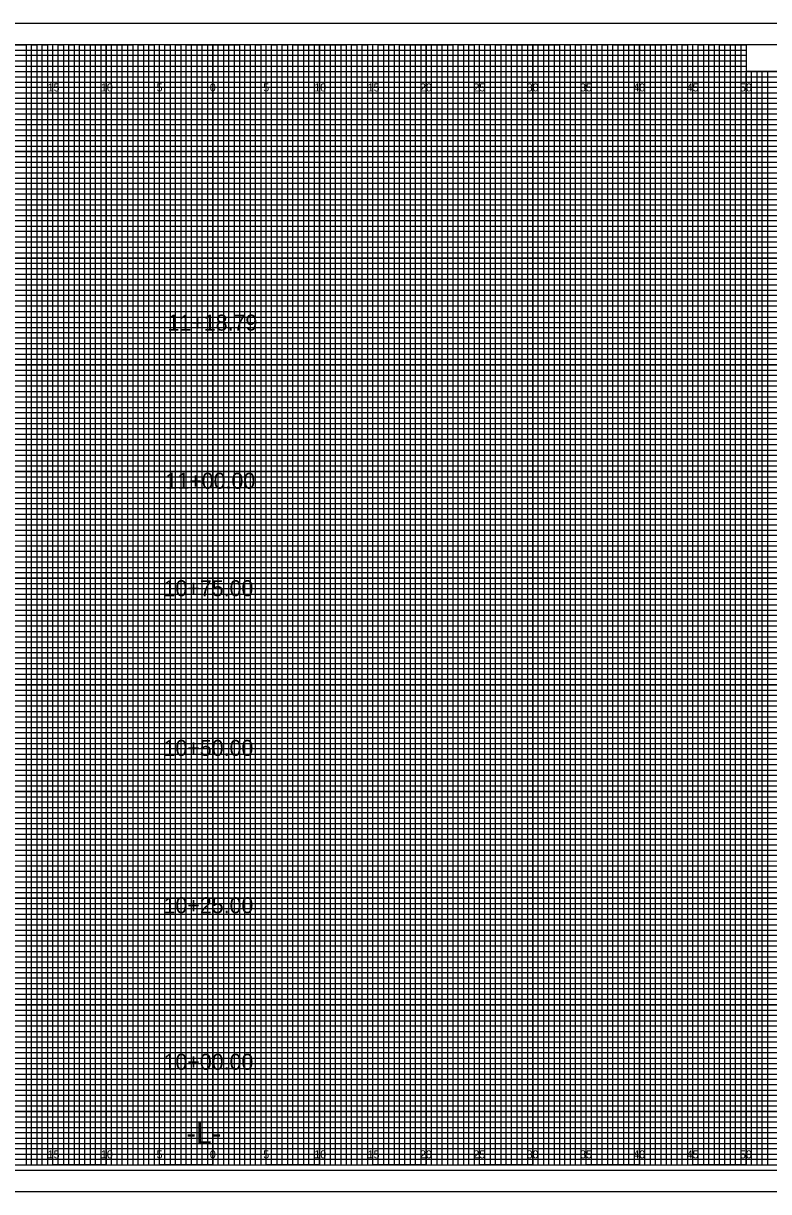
# Model space of a CAD drawing. Extents: x -7 to 205, y -2 to 107.
# Drawn here: x 62.2 to 132.1, y -2.5 to 107 of the extents above; entities that cross this region are included whole.
import ezdxf

# ---------------------------------------------------------------- set-up
doc = ezdxf.new("R2010")
doc.units = 0
for name, color, linetype in [('Prop XS Alignment Label', 7, 'Continuous'), ('Prop XS Offset Labels', 7, 'Continuous'), ('Prop XS Station Labels', 7, 'Continuous'), ('Sheet Cross Section CELL', 7, 'Continuous'), ('Sheet Cross Section Grid Major CELL', 7, 'Continuous'), ('Sheet Cross Section Grid Middle CELL', 7, 'Continuous'), ('Sheet Cross Section Grid Minor 1 CELL', 7, 'Continuous'), ('Sheet Cross Section Grid Minor 2 CELL', 7, 'Continuous'), ('Sheet Cutting Line CELL', 7, 'Continuous'), ('Sheet DOT Grid CELL', 7, 'Continuous'), ('Sheet Plot Border Inside CELL', 7, 'Continuous'), ('Sheet Plot Border Outside CELL', 7, 'Continuous')]:
    doc.layers.add(name, color=color, linetype=linetype)

msp = doc.modelspace()

# ---------------------------------------------------------------- linework, layer by layer
at = {"layer": 'Sheet Cross Section CELL'}
for points in [[(160, 105), (0, 105), (0, 0), (160, 0)], [(140, 105), (130, 105), (130, 102.52), (140, 102.52)]]:
    msp.add_lwpolyline(points, close=True, dxfattribs=at)
at = {"layer": 'Sheet Cross Section Grid Major CELL'}
for p, q in [((65, 105), (60, 105)), ((65, 0), (65, 105)), ((75, 105), (70, 105)), ((70, 105), (70, 0)), ((75, 0), (75, 105)), ((85, 105), (80, 105)), ((80, 105), (80, 0)), ((85, 0), (85, 105)), ((95, 105), (90, 105)), ((90, 105), (90, 0)), ((95, 0), (95, 105)), ((105, 105), (100, 105)), ((100, 105), (100, 0)), ((105, 0), (105, 105)), ((115, 105), (110, 105)), ((110, 105), (110, 0)), ((115, 0), (115, 105)), ((125, 105), (120, 105)), ((120, 105), (120, 0)), ((125, 0), (125, 105)), ((130, 105), (130, 0)), ((70, 0), (65, 0)), ((80, 0), (75, 0)), ((90, 0), (85, 0)), ((100, 0), (95, 0)), ((110, 0), (105, 0)), ((120, 0), (115, 0)), ((130, 0), (125, 0))]:
    msp.add_line(p, q, dxfattribs=at)
for points in [[(0, 100), (160, 100), (160, 95), (0, 95)], [(0, 90), (160, 90), (160, 85), (0, 85)], [(0, 80), (160, 80), (160, 75), (0, 75)], [(0, 70), (160, 70), (160, 65), (0, 65)], [(0, 60), (160, 60), (160, 55), (0, 55)], [(0, 50), (160, 50), (160, 45), (0, 45)], [(0, 40), (160, 40), (160, 35), (0, 35)], [(0, 30), (160, 30), (160, 25), (0, 25)], [(0, 20), (160, 20), (160, 15), (0, 15)], [(0, 10), (160, 10), (160, 5), (0, 5)]]:
    msp.add_lwpolyline(points, dxfattribs=at)
at = {"layer": 'Sheet Cross Section Grid Middle CELL'}
for points in [[(57.5, 105), (62.5, 105), (62.5, 0), (67.5, 0), (67.5, 105), (72.5, 105), (72.5, 0), (77.5, 0), (77.5, 105), (82.5, 105), (82.5, 0), (87.5, 0), (87.5, 105), (92.5, 105), (92.5, 0), (97.5, 0), (97.5, 105), (102.5, 105), (102.5, 0), (107.5, 0), (107.5, 105), (112.5, 105), (112.5, 0), (117.5, 0), (117.5, 105), (122.5, 105), (122.5, 0), (127.5, 0), (127.5, 105), (129.97, 105), (130, 105), (130, 102.5), (132.5, 102.5)], [(0, 102.5), (137.5, 102.5)], [(0, 92.5), (160, 92.5), (160, 97.5), (0, 97.5)], [(0, 82.5), (160, 82.5), (160, 87.5), (0, 87.5)], [(0, 72.5), (160, 72.5), (160, 77.5), (0, 77.5)], [(0, 62.5), (160, 62.5), (160, 67.5), (0, 67.5)], [(0, 52.5), (160, 52.5), (160, 57.5), (0, 57.5)], [(0, 42.5), (160, 42.5), (160, 47.5), (0, 47.5)], [(0, 32.5), (160, 32.5), (160, 37.5), (0, 37.5)], [(0, 22.5), (160, 22.5), (160, 27.5), (0, 27.5)], [(0, 12.5), (160, 12.5), (160, 17.5), (0, 17.5)], [(0, 2.5), (160, 2.5), (160, 7.5), (0, 7.5)]]:
    msp.add_lwpolyline(points, dxfattribs=at)
at = {"layer": 'Sheet Cross Section Grid Minor 1 CELL'}
for p, q in [((0, 104.5), (130, 104.5)), ((130, 104.5), (130, 103.99)), ((130, 103.99), (0, 103.99)), ((0, 103.5), (130, 103.5)), ((130, 102.95), (0, 102.95)), ((130, 103.5), (130, 102.95)), ((0, 102), (160, 102))]:
    msp.add_line(p, q, dxfattribs=at)
for points in [[(0, 101.5), (135, 101.5), (160, 101.5), (160, 101), (0, 101)], [(0, 100.5), (160, 100.5), (160, 99.5), (0, 99.5)], [(0, 99), (160, 99), (160, 98.5), (0, 98.49)], [(0, 98), (160, 98), (160, 97), (0, 97)], [(0, 96.5), (160, 96.5), (160, 96), (0, 96)], [(0, 95.5), (160, 95.5), (160, 94.5), (0, 94.5)], [(0, 94), (160, 94), (160, 93.5), (0, 93.5)], [(0, 93), (160, 93), (160, 92), (0, 92)], [(0, 91.5), (160, 91.5), (160, 91), (0, 91)], [(0, 90.5), (160, 90.5), (160, 89.5), (0, 89.5)], [(0, 89), (160, 89), (160, 88.5), (0, 88.5)], [(0, 88), (160, 88), (160, 86.98), (160, 86.5), (160, 86), (0, 86)], [(0, 87), (160, 87), (160, 86.5), (0, 86.5)], [(0, 85.5), (160, 85.5), (160, 84.5), (0, 84.52)], [(0, 84.52), (160, 84.5), (160, 84), (0, 84)], [(0, 83.5), (160, 83.5), (160, 83), (0, 83)], [(0, 82), (160, 82), (160, 81.5), (0, 81.5)], [(0, 81), (160, 81), (160, 80.5), (0, 80.5)], [(-0.04, 79.45), (160, 79.45), (160, 78.94), (-0.04, 78.94)], [(0, 78.5), (160, 78.5), (160, 78), (0, 78)], [(0, 77), (160, 77), (160, 76.5), (0, 76.5)], [(0, 76), (160, 76), (160, 75.5), (0, 75.5)], [(0, 74.5), (160, 74.5), (160, 74), (0, 74)], [(0, 73.5), (160, 73.5), (160, 73), (0, 73)], [(0, 72), (160, 72), (160, 71.5), (0, 71.5)], [(0, 71), (160, 71), (160, 70.5), (0, 70.5)], [(0, 69.5), (160, 69.5), (160, 68.99), (0, 69)], [(0, 68.5), (160, 68.5), (160, 68), (0, 68)], [(0, 67), (160, 67), (160, 66.5), (0, 66.5)], [(0, 66), (160, 66), (160, 65.5), (0, 65.5)], [(0, 64.5), (160, 64.5), (160, 64), (0, 64)], [(0, 63.5), (160, 63.5), (160, 63), (0, 63)], [(0, 62), (160, 62), (160, 61.5), (0, 61.5)], [(0, 61), (160, 61), (160, 60.5), (0, 60.5)], [(0, 59.5), (160, 59.5), (160, 59), (0, 59)], [(0, 58.5), (160.03, 58.45), (160, 58), (0, 58)], [(0, 57), (160, 57), (160, 56.5), (0, 56.5)], [(0, 56), (160, 56), (160, 55.5), (0, 55.5)], [(0, 54.5), (160, 54.5), (160, 54), (0, 54)], [(0, 53.5), (160, 53.5), (160, 53), (0, 53)], [(0, 52), (160, 52), (160, 51.5), (0, 51.5)], [(0, 51), (160, 51), (160, 50.5), (0, 50.5)], [(0, 49.5), (160, 49.5), (160, 49), (0, 49)], [(0, 48.5), (160, 48.5), (160, 48), (0, 48)], [(0, 47), (160, 47), (160, 46.5), (0, 46.5)], [(0, 46), (160, 46), (160, 45.5), (0, 45.5)], [(0, 44.5), (160, 44.5), (160, 44), (0, 44)], [(0, 43.5), (160, 43.5), (160, 43), (0, 43)], [(0, 42), (160, 42), (160, 41.5), (0, 41.5)], [(0, 41), (160, 41), (160, 40.5), (0, 40.5)], [(0, 39.5), (160, 39.5), (160, 38.99), (0, 39)], [(0, 38.5), (160, 38.5), (160, 38), (0, 38)], [(0, 37), (160, 37), (160, 36.5), (0, 36.5)], [(0, 36), (160, 36), (160, 35.5), (0, 35.5)], [(0, 34.5), (160, 34.5), (160, 34), (0, 34)], [(0, 33.5), (160, 33.5), (160, 33), (0, 33)], [(0, 32), (160, 32), (160, 31.5), (0, 31.5)], [(0, 31), (160, 31), (160, 30.5), (0, 30.5)], [(0, 29.5), (160, 29.5), (160, 29), (0, 29)], [(0, 28.5), (160.03, 28.46), (160, 28), (0, 28)], [(0, 27), (160, 27), (160, 26.5), (0, 26.5)], [(0, 26), (160, 26), (160, 25.5), (0, 25.5)], [(0, 24.5), (160, 24.5), (160, 24), (0, 24)], [(0, 23.5), (160, 23.5), (160, 23), (0, 23)], [(0, 22), (160, 22), (160, 21.5), (0, 21.5)], [(0, 21), (160, 21), (160, 20.5), (0, 20.5)], [(0, 19.5), (160, 19.5), (160, 19), (0, 19)], [(0, 18.5), (160, 18.5), (160, 18), (0, 18)], [(0, 17), (160, 17), (160, 16.5), (0, 16.5)], [(0, 16), (160, 16), (160, 15.5), (0, 15.5)], [(0, 14.5), (160, 14.5), (160, 14), (0, 14)], [(0, 13.5), (160, 13.5), (160, 13), (0, 13)], [(0, 12), (160, 12), (160, 11.5), (0, 11.5)], [(0, 11), (160, 11), (160, 10.5), (0, 10.5)], [(0, 9.5), (160, 9.5), (160, 9), (0, 9)], [(0, 8.5), (160, 8.5), (160, 8), (0, 8)], [(0, 7), (160, 7), (160, 6.5), (0, 6.5)], [(0, 6), (160, 6), (160, 5.5), (0, 5.5)], [(0, 4.5), (160, 4.5), (160, 4), (0, 4)], [(0, 3.5), (160, 3.5), (160, 3), (0, 3)], [(0, 2), (160, 2), (160, 1.5), (0, 1.5)], [(0, 1), (160, 1), (160, 0.5), (0, 0.5)]]:
    msp.add_lwpolyline(points, dxfattribs=at)
at = {"layer": 'Sheet Cross Section Grid Minor 2 CELL'}
for points in [[(62.5, 0), (63, 0), (63, 105), (63.5, 105), (63.5, 0)], [(63.5, 0), (64, 0), (64, 105), (64.5, 105), (64.5, 0)], [(65, 0), (65.5, 0), (65.5, 105), (66, 105), (66, 0)], [(66, 0), (66.5, 0), (66.5, 105), (67, 105), (67, 0)], [(67.5, 0), (68, 0), (68, 105), (68.5, 105), (68.5, 0)], [(68.5, 0), (69, 0), (69, 105), (69.5, 105), (69.5, 0)], [(70, 0), (70.5, 0), (70.5, 105), (71, 105), (71, 0)], [(71, 0), (71.5, 0), (71.5, 105), (72, 105), (72, 0)], [(72.5, 0), (73, 0), (73, 105), (73.5, 105), (73.5, 0)], [(73.5, 0), (74, 0), (74, 105), (74.5, 105), (74.5, 0)], [(75, 0), (75.5, 0), (75.5, 105), (76, 105), (76, 0)], [(76, 0), (76.5, 0), (76.5, 105), (77, 105), (77, 0)], [(77.5, 0), (78, 0), (78, 105), (78.5, 105), (78.5, 0)], [(78.5, 0), (79, 0), (79, 105), (79.5, 105), (79.5, 0)], [(80, 0), (80.5, 0), (80.5, 105), (81, 105), (81, 0)], [(81, 0), (81.5, 0), (81.5, 105), (82, 105), (82, 0)], [(82.5, 0), (83, 0), (83, 105), (83.5, 105), (83.5, 0)], [(83.5, 0), (84, 0), (84, 105), (84.5, 105), (84.5, 0)], [(85, 0), (85.5, 0), (85.5, 105), (86, 105), (86, 0)], [(86, 0), (86.5, 0), (86.5, 105), (87, 105), (87, 0)], [(87.5, 0), (88, 0), (88, 105), (88.5, 105), (88.5, 0)], [(88.5, 0), (89, 0), (89, 105), (89.5, 105), (89.5, 0)], [(90, 0), (90.5, 0), (90.5, 105), (91, 105), (91, 0)], [(91, 0), (91.5, 0), (91.5, 105), (92, 105), (92, 0)], [(92.5, 0), (93, 0), (93, 105), (93.5, 105), (93.5, 0)], [(93.5, 0), (94, 0), (94, 105), (94.5, 105), (94.5, 0)], [(95, 0), (95.5, 0), (95.5, 105), (96, 105), (96, 0)], [(96, 0), (96.5, 0), (96.5, 105), (97, 105), (97, 0)], [(97.5, 0), (98, 0), (98, 105), (98.5, 105), (98.5, 0)], [(98.5, 0), (99, 0), (99, 105), (99.5, 105), (99.5, 0)], [(100, 0), (100.5, 0), (100.5, 105), (101, 105), (101, 0)], [(101, 0), (101.5, 0), (101.5, 105), (102, 105), (102, 0)], [(102.5, 0), (103, 0), (103, 105), (103.5, 105), (103.5, 0)], [(103.5, 0), (104, 0), (104, 105), (104.5, 105), (104.5, 0)], [(105, 0), (105.5, 0), (105.5, 105), (106, 105), (106, 0)], [(106, 0), (106.5, 0), (106.5, 105), (107, 105), (107, 0)], [(107.5, 0), (108, 0), (108, 105), (108.5, 105), (108.5, 0)], [(108.5, 0), (109, 0), (109, 105), (109.5, 105), (109.5, 0)], [(110, 0), (110.5, 0), (110.5, 105), (111, 105), (111, 0)], [(111, 0), (111.5, 0), (111.5, 105), (112, 105), (112, 0)], [(112.5, 0), (113, 0), (113, 105), (113.5, 105), (113.5, 0)], [(113.5, 0), (114, 0), (114, 105), (114.5, 105), (114.5, 0)], [(115, 0), (115.5, 0), (115.5, 105), (116, 105), (116, 0)], [(116, 0), (116.5, 0), (116.5, 105), (117, 105), (117, 0)], [(117.5, 0), (118, 0), (118, 105), (118.5, 105), (118.5, 0)], [(118.5, 0), (119, 0), (119, 105), (119.5, 105), (119.5, 0)], [(120, 0), (120.5, 0), (120.5, 105), (121, 105), (121, 0)], [(121, 0), (121.5, 0), (121.5, 105), (122, 105), (122, 0)], [(122.5, 0), (123, 0), (123, 105), (123.5, 105), (123.5, 0)], [(123.5, 0), (124, 0), (124, 105), (124.5, 105), (124.5, 0)], [(125, 0), (125.5, 0), (125.5, 105), (126, 105), (126, 0)], [(126, 0), (126.5, 0), (126.5, 105), (127, 105), (127, 0)], [(127.5, 0), (128, 0), (128, 105), (128.5, 105), (128.5, 0)], [(128.5, 0), (129, 0), (129, 105), (129.5, 105), (129.5, 0)], [(130, 0), (130.5, 0), (130.5, 102.5), (131.01, 102.5), (131.01, 0)], [(131, 0), (131.5, 0), (131.5, 102.5), (132, 102.5), (132, 0)]]:
    msp.add_lwpolyline(points, dxfattribs=at)
at = {"layer": 'Sheet Cutting Line CELL'}
for p, q in [((161.65, 107), (-6.7, 107)), ((-6.7, -2.5), (161.65, -2.5))]:
    msp.add_line(p, q, dxfattribs=at)
at = {"layer": 'Sheet DOT Grid CELL'}
for p, q in [((65, 0), (65, 105)), ((70, 0), (70, 105)), ((75, 0), (75, 105)), ((80, 0), (80, 105)), ((85, 0), (85, 105)), ((90, 0), (90, 105)), ((95, 0), (95, 105)), ((100, 0), (100, 105)), ((105, 0), (105, 105)), ((110, 0), (110, 105)), ((115, 0), (115, 105)), ((120, 0), (120, 105)), ((125, 0), (125, 105)), ((130, 0), (130, 102.34)), ((0, 100), (160, 100)), ((0, 95), (160, 95)), ((0, 90), (160, 90)), ((0, 85), (160, 85)), ((0, 80), (160, 80)), ((0, 75), (160, 75)), ((0, 70), (160, 70)), ((0, 65), (160, 65)), ((0, 60), (160, 60)), ((0, 55), (160, 55)), ((0, 50), (160, 50)), ((0, 45), (160, 45)), ((0, 40), (160, 40)), ((0, 35), (160, 35)), ((0, 30), (160, 30)), ((0, 25), (160, 25)), ((0, 20), (160, 20)), ((0, 15), (160, 15)), ((0, 10), (160, 10)), ((0, 5), (160, 5))]:
    msp.add_line(p, q, dxfattribs=at)
at = {"layer": 'Sheet Plot Border Inside CELL'}
msp.add_lwpolyline([(-5.4, -0.5), (161.2, -0.5), (161.2, 105), (-5.4, 105)], close=True, dxfattribs=at)
at = {"layer": 'Sheet Plot Border Outside CELL'}
msp.add_lwpolyline([(-6.7, -2.5), (161.65, -2.5), (161.65, 107), (-6.7, 107)], close=True, dxfattribs=at)

# ---------------------------------------------------------------- texts
at = {"layer": 'Prop XS Alignment Label'}
msp.add_text('-L-', height=2, dxfattribs=at).set_placement((77.53, 2))
at = {"layer": 'Prop XS Offset Labels'}
for s, p in [('15', (64.53, 100.62)), ('10', (69.52, 100.62)), ('5', (74.74, 100.62)), ('0', (79.73, 100.62)), ('0', (79.73, 100.62)), ('5', (84.74, 100.62)), ('10', (89.52, 100.62)), ('15', (94.53, 100.62)), ('20', (99.43, 100.62)), ('25', (104.44, 100.62)), ('30', (109.43, 100.62)), ('35', (114.44, 100.62)), ('40', (119.43, 100.62)), ('45', (124.44, 100.62)), ('50', (129.43, 100.62)), ('15', (64.53, 0.62)), ('10', (69.52, 0.62)), ('5', (74.74, 0.62)), ('0', (79.73, 0.62)), ('0', (79.73, 0.62)), ('5', (84.74, 0.62)), ('10', (89.52, 0.62)), ('15', (94.53, 0.62)), ('20', (99.43, 0.62)), ('25', (104.44, 0.62)), ('30', (109.43, 0.62)), ('35', (114.44, 0.62)), ('40', (119.43, 0.62)), ('45', (124.44, 0.62)), ('50', (129.43, 0.62))]:
    msp.add_text(s, height=0.75, dxfattribs=at).set_placement(p)
at = {"layer": 'Prop XS Station Labels'}
for s, p in [('11+18.79', (75.76, 78.2)), ('11+00.00', (75.57, 63.38)), ('10+75.00', (75.39, 53.31)), ('10+50.00', (75.39, 38.34)), ('10+25.00', (75.39, 23.59)), ('10+00.00', (75.39, 8.92))]:
    msp.add_text(s, height=1.5, dxfattribs=at).set_placement(p)

doc.saveas('drawing.dxf')
